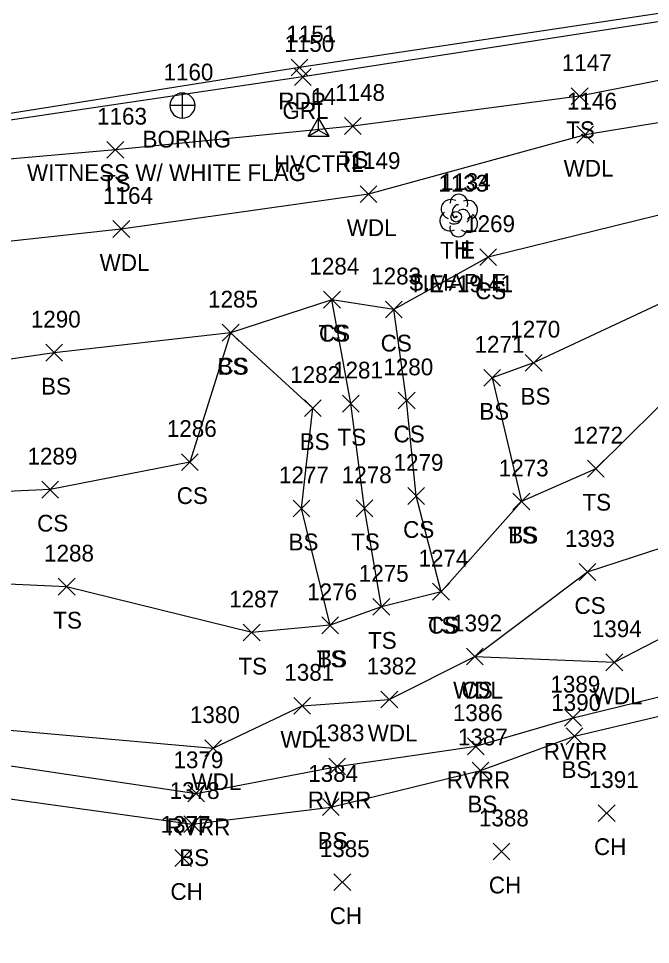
# Model space of a CAD drawing. Extents: x 1502119 to 1504100, y 606168 to 606406.
# Drawn here: x 1503780.9 to 1503856.3, y 606184.3 to 606294.7 of the extents above; entities that cross this region are included whole.
import ezdxf

# ---------------------------------------------------------------- set-up
doc = ezdxf.new("R2010")
doc.units = 0
for name, color, linetype in [('C_A', 7, 'Continuous'), ('C_C', 7, 'Continuous'), ('C_I', 7, 'Continuous'), ('CBP', 7, 'Continuous'), ('CPSM', 7, 'Continuous'), ('G_A', 7, 'Continuous'), ('G_C', 7, 'Continuous'), ('G_I', 7, 'Continuous'), ('GA_P', 7, 'Continuous'), ('L_A', 7, 'Continuous'), ('L_C', 7, 'Continuous'), ('L_I', 7, 'Continuous'), ('L_TIC', 7, 'Continuous'), ('LAWA', 7, 'Continuous'), ('LAWE', 7, 'Continuous'), ('LELB', 7, 'Continuous'), ('LTD', 7, 'Continuous'), ('P_A', 7, 'Continuous'), ('P_I', 7, 'Continuous'), ('P_TIC', 7, 'Continuous'), ('PET', 7, 'Continuous'), ('R_A', 7, 'Continuous'), ('R_I', 7, 'Continuous'), ('R_TIC', 7, 'Continuous'), ('RGR', 7, 'Continuous')]:
    doc.layers.add(name, color=color, linetype=linetype)

msp = doc.modelspace()

# ---------------------------------------------------------------- linework, layer by layer
at = {"layer": 'CBP'}
for radius in [0.625, 0.0833]:
    msp.add_circle((1503833.1, 606271.05), radius, dxfattribs=at)
at = {"layer": 'CPSM'}
for p, q in [((1503815.43, 606280.67), (1503816.68, 606282.84)), ((1503817.93, 606280.67), (1503816.68, 606282.84)), ((1503816.68, 606281.39), (1503816.68, 606282.84)), ((1503815.43, 606280.67), (1503816.68, 606281.39)), ((1503816.68, 606281.39), (1503816.68, 606281.39)), ((1503816.68, 606281.39), (1503817.93, 606280.67)), ((1503815.43, 606280.67), (1503817.93, 606280.67))]:
    msp.add_line(p, q, dxfattribs=at)
at = {"layer": 'GA_P'}
for p, q in [((1503800.45, 606284.31), (1503800.45, 606285.81)), ((1503800.45, 606284.31), (1503798.95, 606284.31)), ((1503801.95, 606284.31), (1503800.45, 606284.31)), ((1503800.45, 606282.81), (1503800.45, 606284.31))]:
    msp.add_line(p, q, dxfattribs=at)
for start, end in [(90, 180), (0, 90), (180, 270), (270, 0)]:
    msp.add_arc((1503800.45, 606284.31), 1.5, start, end, dxfattribs=at)
at = {"layer": 'L_TIC'}
for points in [[(1503846.82, 606284.43), (1503848.82, 606286.43)], [(1503848.82, 606284.43), (1503846.82, 606286.43)], [(1503819.78, 606280.87), (1503821.78, 606282.87)], [(1503821.78, 606280.87), (1503819.78, 606282.87)], [(1503847.49, 606279.84), (1503849.49, 606281.84)], [(1503849.49, 606279.84), (1503847.49, 606281.84)], [(1503791.45, 606278.04), (1503793.45, 606280.04)], [(1503793.45, 606278.04), (1503791.45, 606280.04)], [(1503821.63, 606272.75), (1503823.63, 606274.75)], [(1503823.63, 606272.75), (1503821.63, 606274.75)], [(1503792.16, 606268.59), (1503794.16, 606270.59)], [(1503794.16, 606268.59), (1503792.16, 606270.59)], [(1503835.9, 606265.22), (1503837.9, 606267.22)], [(1503837.9, 606265.22), (1503835.9, 606267.22)], [(1503817.28, 606260.16), (1503819.28, 606262.16)], [(1503819.28, 606260.16), (1503817.28, 606262.16)], [(1503817.28, 606260.16), (1503819.28, 606262.16)], [(1503819.28, 606260.16), (1503817.28, 606262.16)], [(1503824.65, 606258.98), (1503826.65, 606260.98)], [(1503826.65, 606258.98), (1503824.65, 606260.98)], [(1503824.65, 606258.98), (1503826.65, 606260.98)], [(1503826.65, 606258.98), (1503824.65, 606260.98)], [(1503805.2, 606256.22), (1503807.2, 606258.22)], [(1503807.2, 606256.22), (1503805.2, 606258.22)], [(1503805.2, 606256.22), (1503807.2, 606258.22)], [(1503807.2, 606256.22), (1503805.2, 606258.22)], [(1503784.15, 606253.84), (1503786.15, 606255.84)], [(1503786.15, 606253.84), (1503784.15, 606255.84)], [(1503841.33, 606252.64), (1503843.33, 606254.64)], [(1503843.33, 606252.64), (1503841.33, 606254.64)], [(1503836.4, 606250.84), (1503838.4, 606252.84)], [(1503838.4, 606250.84), (1503836.4, 606252.84)], [(1503814.99, 606247.23), (1503816.99, 606249.23)], [(1503816.99, 606247.23), (1503814.99, 606249.23)], [(1503819.54, 606247.76), (1503821.54, 606249.76)], [(1503821.54, 606247.76), (1503819.54, 606249.76)], [(1503826.19, 606248.14), (1503828.19, 606250.14)], [(1503828.19, 606248.14), (1503826.19, 606250.14)], [(1503800.33, 606240.79), (1503802.33, 606242.79)], [(1503802.33, 606240.79), (1503800.33, 606242.79)], [(1503848.74, 606240), (1503850.74, 606242)], [(1503850.74, 606240), (1503848.74, 606242)], [(1503783.67, 606237.5), (1503785.67, 606239.5)], [(1503785.67, 606237.5), (1503783.67, 606239.5)], [(1503827.33, 606236.75), (1503829.33, 606238.75)], [(1503829.33, 606236.75), (1503827.33, 606238.75)], [(1503813.66, 606235.26), (1503815.66, 606237.26)], [(1503815.66, 606235.26), (1503813.66, 606237.26)], [(1503821.15, 606235.27), (1503823.15, 606237.27)], [(1503823.15, 606235.27), (1503821.15, 606237.27)], [(1503839.87, 606236.08), (1503841.87, 606238.08)], [(1503841.87, 606236.08), (1503839.87, 606238.08)], [(1503839.87, 606236.08), (1503841.87, 606238.08)], [(1503841.87, 606236.08), (1503839.87, 606238.08)], [(1503847.76, 606227.68), (1503849.76, 606229.68)], [(1503849.76, 606227.68), (1503847.76, 606229.68)], [(1503785.64, 606225.93), (1503787.64, 606227.93)], [(1503787.64, 606225.93), (1503785.64, 606227.93)], [(1503830.29, 606225.33), (1503832.29, 606227.33)], [(1503832.29, 606225.33), (1503830.29, 606227.33)], [(1503830.29, 606225.33), (1503832.29, 606227.33)], [(1503832.29, 606225.33), (1503830.29, 606227.33)], [(1503823.17, 606223.52), (1503825.17, 606225.52)], [(1503825.17, 606223.52), (1503823.17, 606225.52)], [(1503823.17, 606223.52), (1503825.17, 606225.52)], [(1503825.17, 606223.52), (1503823.17, 606225.52)], [(1503817.07, 606221.32), (1503819.07, 606223.32)], [(1503819.07, 606221.32), (1503817.07, 606223.32)], [(1503817.07, 606221.32), (1503819.07, 606223.32)], [(1503819.07, 606221.32), (1503817.07, 606223.32)], [(1503807.71, 606220.45), (1503809.71, 606222.45)], [(1503809.71, 606220.45), (1503807.71, 606222.45)], [(1503834.31, 606217.59), (1503836.31, 606219.59)], [(1503836.31, 606217.59), (1503834.31, 606219.59)], [(1503834.31, 606217.59), (1503836.31, 606219.59)], [(1503836.31, 606217.59), (1503834.31, 606219.59)], [(1503850.96, 606216.91), (1503852.96, 606218.91)], [(1503852.96, 606216.91), (1503850.96, 606218.91)], [(1503824.12, 606212.47), (1503826.12, 606214.47)], [(1503826.12, 606212.47), (1503824.12, 606214.47)], [(1503813.72, 606211.71), (1503815.72, 606213.71)], [(1503815.72, 606211.71), (1503813.72, 606213.71)], [(1503846.03, 606210.3), (1503848.03, 606212.3)], [(1503848.03, 606210.3), (1503846.03, 606212.3)], [(1503846.21, 606208.11), (1503848.21, 606210.11)], [(1503848.21, 606208.11), (1503846.21, 606210.11)], [(1503803.12, 606206.66), (1503805.12, 606208.66)], [(1503805.12, 606206.66), (1503803.12, 606208.66)], [(1503834.44, 606206.89), (1503836.44, 606208.89)], [(1503836.44, 606206.89), (1503834.44, 606208.89)], [(1503817.9, 606204.49), (1503819.9, 606206.49)], [(1503819.9, 606204.49), (1503817.9, 606206.49)], [(1503834.99, 606204), (1503836.99, 606206)], [(1503836.99, 606204), (1503834.99, 606206)], [(1503801.08, 606201.28), (1503803.08, 606203.28)], [(1503803.08, 606201.28), (1503801.08, 606203.28)], [(1503817.14, 606199.65), (1503819.14, 606201.65)], [(1503819.14, 606199.65), (1503817.14, 606201.65)], [(1503850.04, 606198.92), (1503852.04, 606200.92)], [(1503852.04, 606198.92), (1503850.04, 606200.92)], [(1503800.63, 606197.61), (1503802.63, 606199.61)], [(1503802.63, 606197.61), (1503800.63, 606199.61)], [(1503837.51, 606194.34), (1503839.51, 606196.34)], [(1503839.51, 606194.34), (1503837.51, 606196.34)], [(1503799.53, 606193.57), (1503801.53, 606195.57)], [(1503801.53, 606193.57), (1503799.53, 606195.57)], [(1503818.52, 606190.68), (1503820.52, 606192.68)], [(1503820.52, 606190.68), (1503818.52, 606192.68)]]:
    msp.add_lwpolyline(points, dxfattribs=at)
at = {"layer": 'LAWA'}
for points in [[(1503949.06, 606292.95), (1503922.72, 606291.41), (1503895.88, 606293.14), (1503871.23, 606284.55), (1503848.49, 606280.84), (1503822.63, 606273.75), (1503793.16, 606269.59), (1503770.58, 606267.1), (1503744.52, 606264.72), (1503721.39, 606263.89), (1503714.66, 606265.31), (1503698.22, 606260.24), (1503685.38, 606258.11), (1503660.65, 606259.69), (1503652.68, 606259.1), (1503650.68, 606259.07), (1503643.68, 606257.82), (1503632.11, 606261.1), (1503598.78, 606263.09)], [(1503644.38, 606200.66), (1503661.82, 606197.6), (1503681.92, 606200.3), (1503697.7, 606204.96), (1503718.32, 606211.61), (1503749.72, 606205.75), (1503773.98, 606210.33), (1503804.12, 606207.66), (1503814.72, 606212.71), (1503825.12, 606213.47), (1503835.31, 606218.59), (1503851.96, 606217.91), (1503869.14, 606226.79), (1503894.25, 606229.09), (1503902.71, 606239.52), (1503913.47, 606247.57)]]:
    msp.add_lwpolyline(points, dxfattribs=at)
at = {"layer": 'LAWE'}
msp.add_lwpolyline([(1503614.85, 606213.1), (1503625.62, 606202.51), (1503635.42, 606197.97), (1503642.95, 606193.31), (1503660.89, 606194.04), (1503681.2, 606197.62), (1503698.42, 606201.39), (1503720.62, 606206.39), (1503749.7, 606202.44), (1503775.92, 606206.14), (1503802.08, 606202.28), (1503818.9, 606205.49), (1503835.44, 606207.89), (1503847.03, 606211.3), (1503876.78, 606218.57), (1503896.13, 606221.77), (1503905.66, 606233.48), (1503922.02, 606244.01), (1503934.31, 606243.71)], dxfattribs=at)
at = {"layer": 'LELB'}
for points in [[(1504084.2, 606316.18), (1504049.45, 606313.99), (1504016.18, 606312.8), (1504000.76, 606312.78), (1503990.22, 606311.65), (1503980.1, 606310.35), (1503956.75, 606307.04), (1503915.14, 606300.95), (1503869.77, 606289.77), (1503847.82, 606285.43), (1503820.78, 606281.87), (1503792.45, 606279.04), (1503767.54, 606276.84), (1503743.42, 606274.71), (1503718.48, 606272.4), (1503713.68, 606272.36), (1503654.98, 606271.32), (1503649.47, 606271.35), (1503622.06, 606272.76), (1503601.12, 606274.82)], [(1503984.83, 606255.06), (1503973.29, 606256.69), (1503955.93, 606260.62), (1503952.28, 606267.45), (1503924.4, 606275.03), (1503909.61, 606278), (1503896.78, 606282.99), (1503877.54, 606272.17), (1503862.1, 606272.45), (1503836.9, 606266.22), (1503825.65, 606259.98), (1503818.28, 606261.16), (1503806.2, 606257.22), (1503801.33, 606241.79), (1503784.67, 606238.5), (1503757.1, 606237.25), (1503731.6, 606237.76), (1503710.27, 606237.78), (1503692.02, 606229.45), (1503676.15, 606227.07), (1503663.08, 606221.89), (1503653.08, 606223.12)], [(1503952.28, 606267.45), (1503927.72, 606268.82), (1503911.45, 606264.08), (1503899.94, 606271.83), (1503881.96, 606263.04), (1503860.02, 606261.89), (1503842.33, 606253.64), (1503837.4, 606251.84), (1503840.87, 606237.08)], [(1503824.17, 606224.52), (1503822.15, 606236.27), (1503820.54, 606248.76), (1503818.28, 606261.16)], [(1503831.29, 606226.33), (1503828.33, 606237.75), (1503827.19, 606249.14), (1503825.65, 606259.98)], [(1503930, 606245.46), (1503918.92, 606249.17), (1503904.84, 606258.51), (1503879.8, 606256.17), (1503860.62, 606251.71), (1503849.74, 606241), (1503840.87, 606237.08), (1503831.29, 606226.33), (1503824.17, 606224.52), (1503818.07, 606222.32), (1503808.71, 606221.45), (1503786.64, 606226.93), (1503757.01, 606228.26), (1503733.84, 606223.62), (1503713.55, 606226.86), (1503694.71, 606218.05), (1503680.4, 606213.07), (1503668.25, 606209.35), (1503648.97, 606211.13)], [(1503818.07, 606222.32), (1503814.66, 606236.26), (1503815.99, 606248.23), (1503806.2, 606257.22), (1503785.15, 606254.84), (1503756.29, 606250.66), (1503730.42, 606249.25), (1503703.2, 606245.4)], [(1503835.31, 606218.59), (1503848.76, 606228.68), (1503864.84, 606233.93), (1503891.76, 606242.88), (1503909.15, 606250.27)], [(1503613.71, 606211.71), (1503624.23, 606201.38), (1503628.7, 606194.41), (1503640.82, 606186.16), (1503659.4, 606184.25), (1503680.75, 606191.25), (1503695.72, 606193.45), (1503722.13, 606200.99), (1503749.25, 606197.03), (1503775.84, 606202.19), (1503801.63, 606198.61), (1503818.14, 606200.65), (1503835.99, 606205), (1503847.21, 606209.11), (1503877.12, 606216.19), (1503896.03, 606218.36), (1503907.7, 606226.44), (1503929.55, 606235.83)]]:
    msp.add_lwpolyline(points, dxfattribs=at)
at = {"layer": 'LTD'}
msp.add_line((1503833.38, 606271.24), (1503833.38, 606271.24), dxfattribs=at)
msp.add_line((1503833.38, 606271.24), (1503833.38, 606271.24), dxfattribs=at)
msp.add_arc((1503833.43, 606272.68), 1.05, 335.5272, 180.9563, dxfattribs=at)
for centre, major_axis, ratio, start_param, end_param in [((1503832.59, 606271.91), (1.21, -0.51), 0.895232, 1.570796, 4.712389), ((1503833.18, 606271.7), (-0.208, -0.792), 0.645439, 3.141593, 6.283185), ((1503834.43, 606271.83), (-1.14, -0.48), 0.949671, 1.570796, 4.712389), ((1503832.3, 606270.54), (0.58, -1.04), 0.959034, 3.141593, 6.283185), ((1503833.88, 606271.08), (-0.5, 0.667), 0.989748, 3.141593, 6.283185), ((1503834.38, 606270.41), (-1.09, 0.79), 0.841452, 1.570796, 4.712389), ((1503832.93, 606270.49), (-0.625, -0.083), 0.423636, 0, 3.141593), ((1503833.39, 606269.74), (0.26, 1.06), 0.942809, 1.570796, 4.712389)]:
    msp.add_ellipse(centre, major_axis=major_axis, ratio=ratio, start_param=start_param, end_param=end_param, dxfattribs=at)
at = {"layer": 'P_TIC'}
for points in [[(1503813.4, 606287.86), (1503815.4, 606289.86)], [(1503815.4, 606287.86), (1503813.4, 606289.86)]]:
    msp.add_lwpolyline(points, dxfattribs=at)
at = {"layer": 'PET'}
msp.add_lwpolyline([(1504084.52, 606320.63), (1504050.65, 606320.45), (1504000.43, 606315.8), (1503956.16, 606310.12), (1503915.05, 606304.21), (1503867.85, 606296.91), (1503814.4, 606288.86), (1503766.38, 606281.21), (1503714.75, 606276.43), (1503655.34, 606274.1), (1503622.19, 606275.72), (1503601.58, 606277.52)], dxfattribs=at)
at = {"layer": 'R_TIC'}
for points in [[(1503813.82, 606286.72), (1503815.82, 606288.72)], [(1503815.82, 606286.72), (1503813.82, 606288.72)]]:
    msp.add_lwpolyline(points, dxfattribs=at)
at = {"layer": 'RGR'}
msp.add_lwpolyline([(1504084.44, 606319.87), (1504050.55, 606319.53), (1504000.64, 606315), (1503956.05, 606309.11), (1503915.05, 606302.99), (1503867.97, 606295.96), (1503814.82, 606287.72), (1503766.2, 606280.53), (1503714.79, 606275.76), (1503655.19, 606273.62), (1503622.1, 606275.05), (1503601.6, 606277)], dxfattribs=at)

# ---------------------------------------------------------------- texts
at = {"layer": 'C_A'}
for s, p in [('HVCTRL', (1503811.37, 606276.39)), ('TIE', (1503831.18, 606266.05))]:
    msp.add_text(s, height=2, dxfattribs=at).set_placement(p)
at = {"layer": 'C_C'}
msp.add_text('TIE=19.41', height=2, dxfattribs=at).set_placement((1503827.46, 606262.05))
at = {"layer": 'C_I'}
for s, p in [('14', (1503815.78, 606284.39)), ('1133', (1503830.97, 606274.05))]:
    msp.add_text(s, height=2, dxfattribs=at).set_placement(p)
at = {"layer": 'G_A'}
msp.add_text('BORING', height=2, dxfattribs=at).set_placement((1503795.69, 606279.31))
at = {"layer": 'G_C'}
msp.add_text('WITNESS W/ WHITE FLAG', height=2, dxfattribs=at).set_placement((1503781.91, 606275.31))
at = {"layer": 'G_I'}
msp.add_text('1160', height=2, dxfattribs=at).set_placement((1503798.19, 606287.31))
at = {"layer": 'L_A'}
for s, p in [('TS', (1503846.22, 606280.43)), ('TS', (1503819.19, 606276.87)), ('WDL', (1503845.91, 606275.84)), ('TS', (1503790.86, 606274.04)), ('WDL', (1503820.05, 606268.75)), ('H', (1503832.82, 606266.24)), ('WDL', (1503790.58, 606264.59)), ('CS', (1503835.35, 606261.22)), ('TS', (1503816.69, 606256.16)), ('CS', (1503816.73, 606256.16)), ('CS', (1503824.09, 606254.98)), ('CS', (1503824.09, 606254.98)), ('CS', (1503804.64, 606252.22)), ('BS', (1503804.64, 606252.22)), ('BS', (1503783.59, 606249.84)), ('BS', (1503840.77, 606248.64)), ('BS', (1503835.85, 606246.84)), ('CS', (1503825.63, 606244.14)), ('BS', (1503814.43, 606243.23)), ('TS', (1503818.95, 606243.76)), ('CS', (1503799.77, 606236.79)), ('TS', (1503848.15, 606236)), ('CS', (1503783.12, 606233.5)), ('CS', (1503826.77, 606232.75)), ('TS', (1503839.28, 606232.08)), ('BS', (1503839.31, 606232.08)), ('BS', (1503813.1, 606231.26)), ('TS', (1503820.56, 606231.27)), ('CS', (1503847.2, 606223.68)), ('TS', (1503785.05, 606221.93)), ('TS', (1503829.7, 606221.33)), ('CS', (1503829.73, 606221.33)), ('TS', (1503822.58, 606219.52)), ('TS', (1503822.58, 606219.52)), ('TS', (1503816.48, 606217.32)), ('BS', (1503816.51, 606217.32)), ('TS', (1503807.12, 606216.45)), ('WDL', (1503832.73, 606213.59)), ('CS', (1503833.75, 606213.59)), ('WDL', (1503849.38, 606212.91)), ('WDL', (1503812.14, 606207.71)), ('WDL', (1503822.54, 606208.47)), ('RVRR', (1503843.54, 606206.3)), ('BS', (1503845.65, 606204.11)), ('WDL', (1503801.53, 606202.66)), ('RVRR', (1503831.96, 606202.89)), ('RVRR', (1503815.41, 606200.49)), ('BS', (1503834.43, 606200)), ('RVRR', (1503798.59, 606197.28)), ('BS', (1503816.58, 606195.65)), ('CH', (1503849.53, 606194.92)), ('BS', (1503800.07, 606193.61)), ('CH', (1503836.99, 606190.34)), ('CH', (1503799.02, 606189.57)), ('CH', (1503818.01, 606186.68))]:
    msp.add_text(s, height=2, dxfattribs=at).set_placement(p)
at = {"layer": 'L_C'}
msp.add_text('S.MAPLE', height=2, dxfattribs=at).set_placement((1503827.45, 606262.24))
at = {"layer": 'L_I'}
for s, p in [('1147', (1503845.69, 606288.43)), ('1148', (1503818.65, 606284.87)), ('1146', (1503846.31, 606283.84)), ('1163', (1503790.27, 606282.04)), ('1149', (1503820.5, 606276.75)), ('1134', (1503831.26, 606274.24)), ('1164', (1503790.99, 606272.59)), ('1269', (1503834.16, 606269.22)), ('1284', (1503815.59, 606264.16)), ('1284', (1503815.59, 606264.16)), ('1283', (1503822.96, 606262.98)), ('1283', (1503822.96, 606262.98)), ('1285', (1503803.51, 606260.22)), ('1285', (1503803.51, 606260.22)), ('1290', (1503782.37, 606257.84)), ('1270', (1503839.55, 606256.64)), ('1271', (1503835.28, 606254.84)), ('1281', (1503818.41, 606251.76)), ('1280', (1503824.41, 606252.14)), ('1282', (1503813.3, 606251.23)), ('1286', (1503798.59, 606244.79)), ('1272', (1503847.04, 606244)), ('1289', (1503781.97, 606241.5)), ('1279', (1503825.63, 606240.75)), ('1273', (1503838.17, 606240.08)), ('1273', (1503838.17, 606240.08)), ('1277', (1503811.96, 606239.26)), ('1278', (1503819.45, 606239.27)), ('1393', (1503846.07, 606231.68)), ('1288', (1503783.95, 606229.93)), ('1274', (1503828.6, 606229.33)), ('1274', (1503828.6, 606229.33)), ('1275', (1503821.48, 606227.52)), ('1275', (1503821.48, 606227.52)), ('1276', (1503815.32, 606225.32)), ('1276', (1503815.32, 606225.32)), ('1287', (1503806.02, 606224.45)), ('1392', (1503832.61, 606221.59)), ('1392', (1503832.61, 606221.59)), ('1394', (1503849.27, 606220.91)), ('1382', (1503822.43, 606216.47)), ('1381', (1503812.6, 606215.71)), ('1389', (1503844.33, 606214.3)), ('1390', (1503844.43, 606212.11)), ('1386', (1503832.7, 606210.89)), ('1380', (1503801.34, 606210.66)), ('1383', (1503816.2, 606208.49)), ('1387', (1503833.3, 606208)), ('1379', (1503799.38, 606205.28)), ('1384', (1503815.45, 606203.65)), ('1391', (1503848.91, 606202.92)), ('1378', (1503798.93, 606201.61)), ('1377', (1503797.84, 606197.57)), ('1388', (1503835.81, 606198.34)), ('1385', (1503816.83, 606194.68))]:
    msp.add_text(s, height=2, dxfattribs=at).set_placement(p)
at = {"layer": 'P_A'}
msp.add_text('RDP', height=2, dxfattribs=at).set_placement((1503811.88, 606283.86))
at = {"layer": 'P_I'}
msp.add_text('1151', height=2, dxfattribs=at).set_placement((1503812.84, 606291.86))
at = {"layer": 'R_A'}
msp.add_text('GRL', height=2, dxfattribs=at).set_placement((1503812.37, 606282.72))
at = {"layer": 'R_I'}
msp.add_text('1150', height=2, dxfattribs=at).set_placement((1503812.61, 606290.72))

doc.saveas('drawing.dxf')
